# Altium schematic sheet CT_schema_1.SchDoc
size 559 x 508 mm
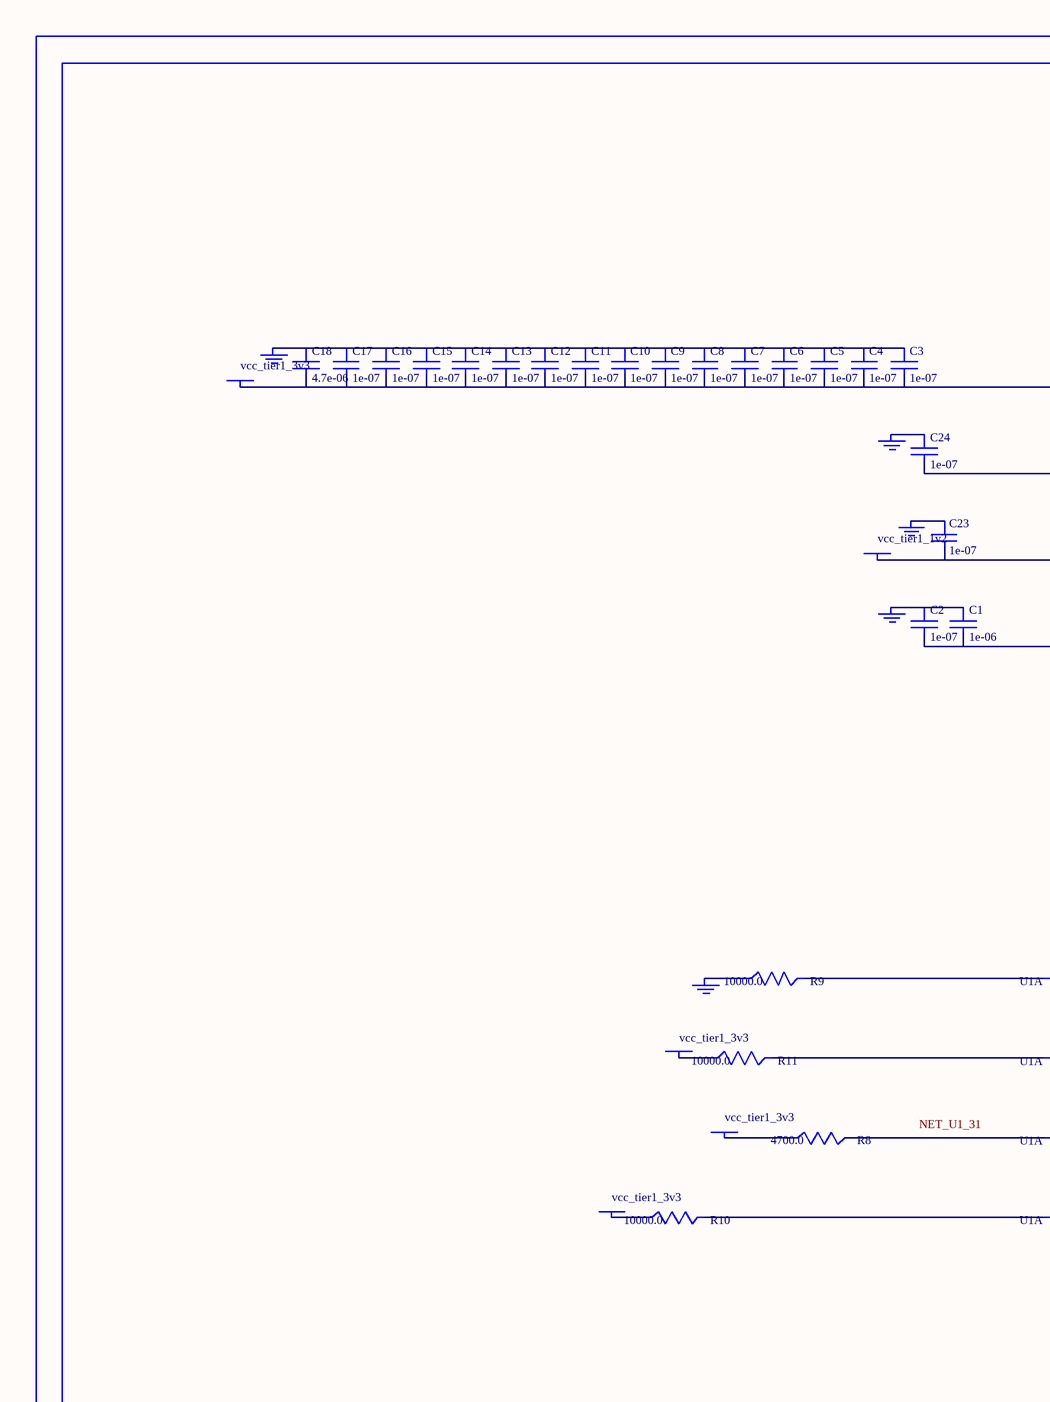
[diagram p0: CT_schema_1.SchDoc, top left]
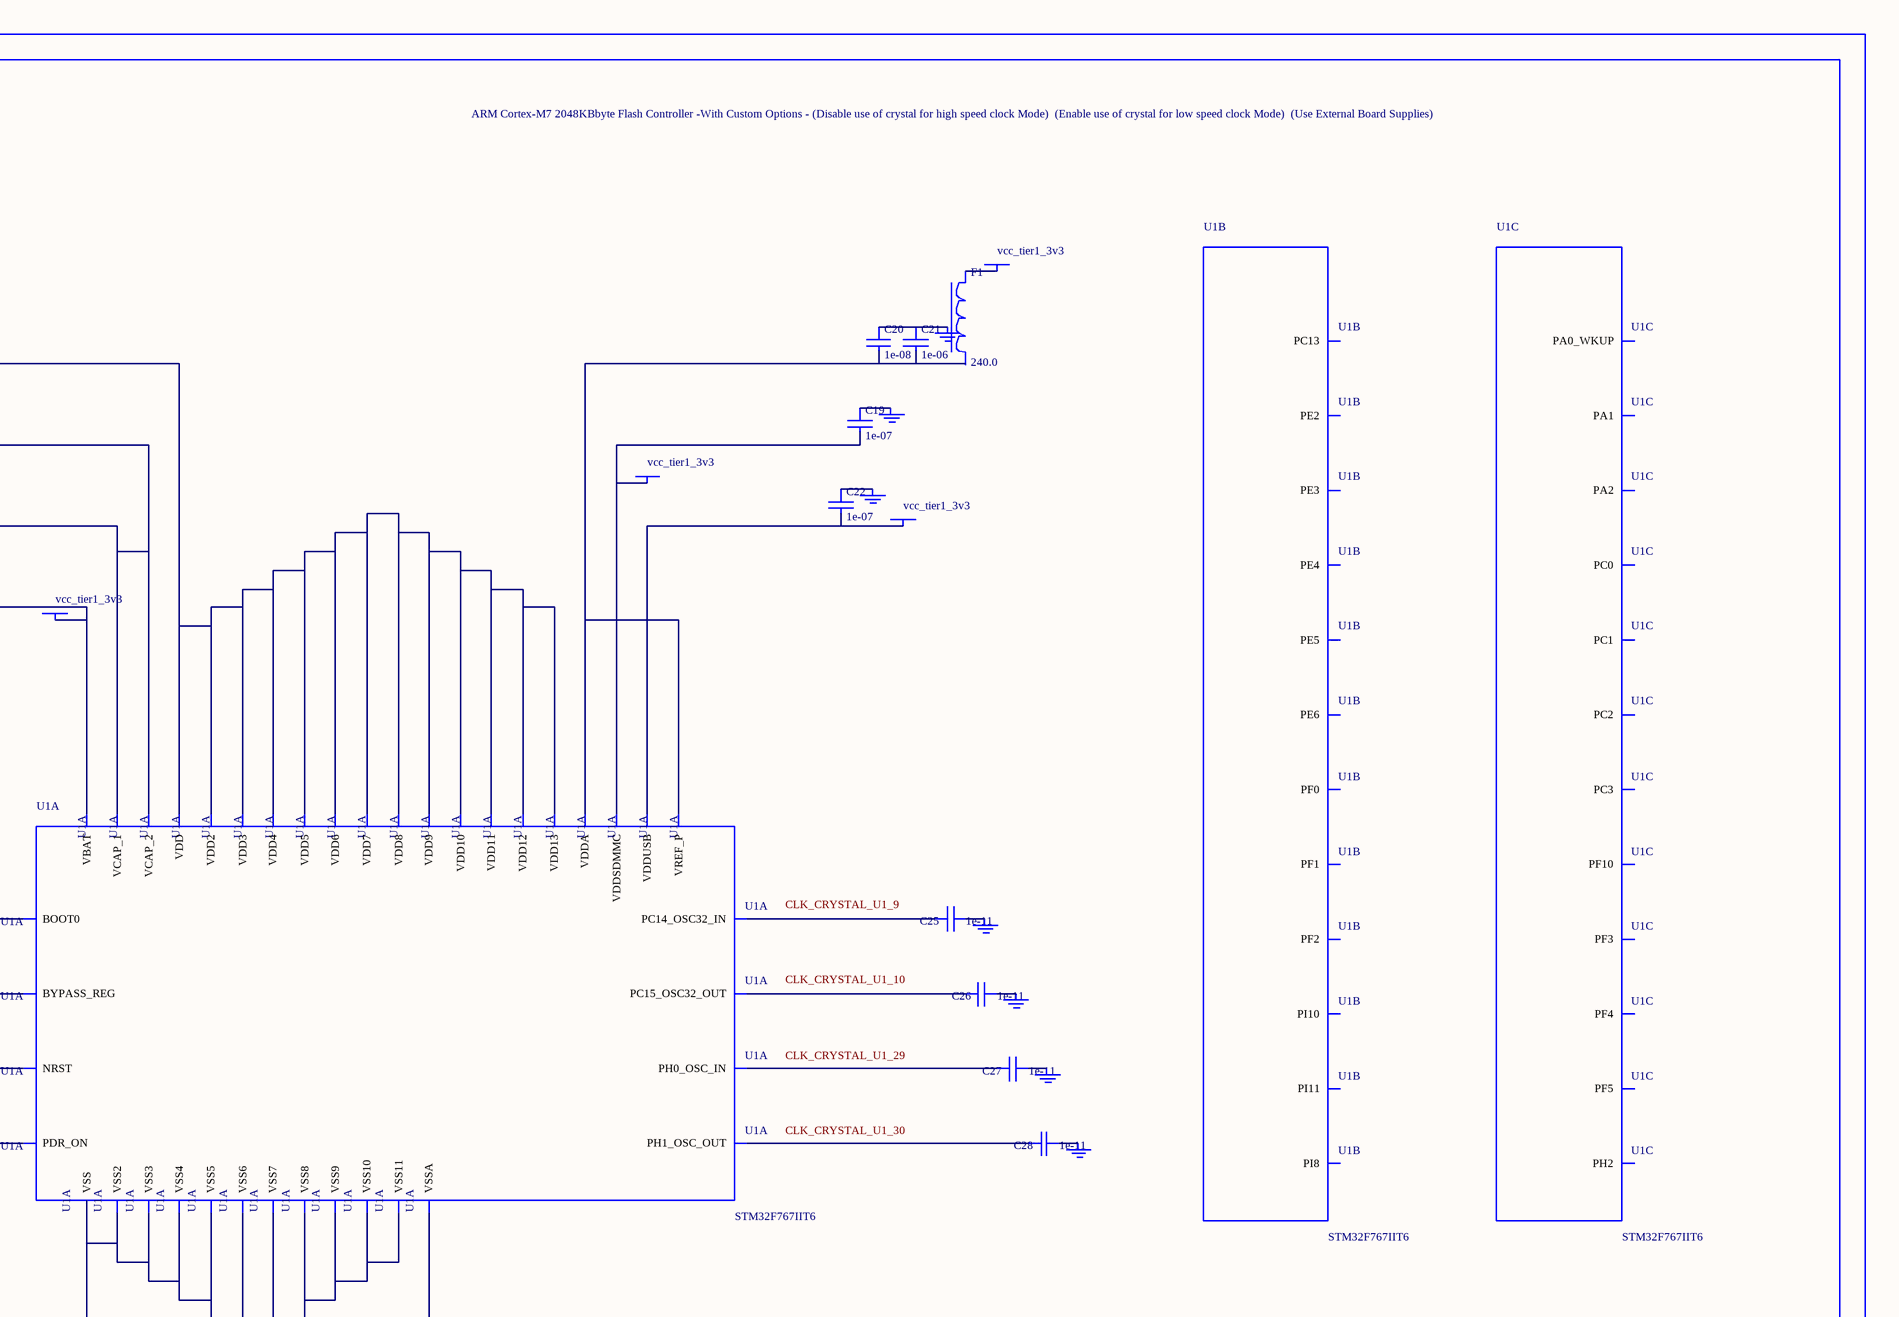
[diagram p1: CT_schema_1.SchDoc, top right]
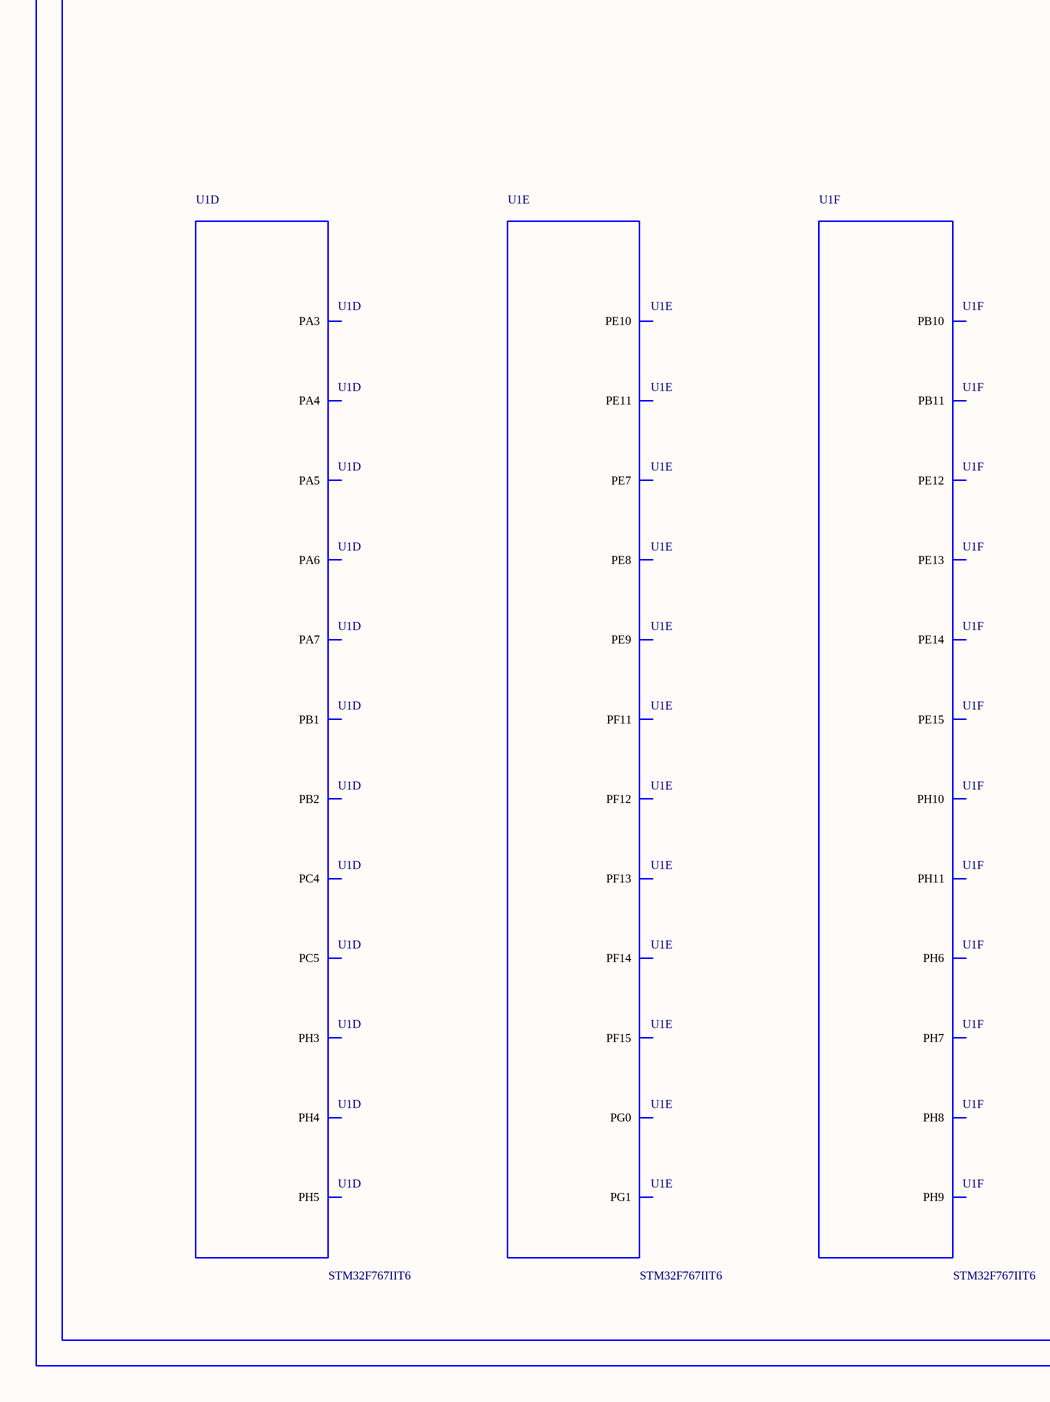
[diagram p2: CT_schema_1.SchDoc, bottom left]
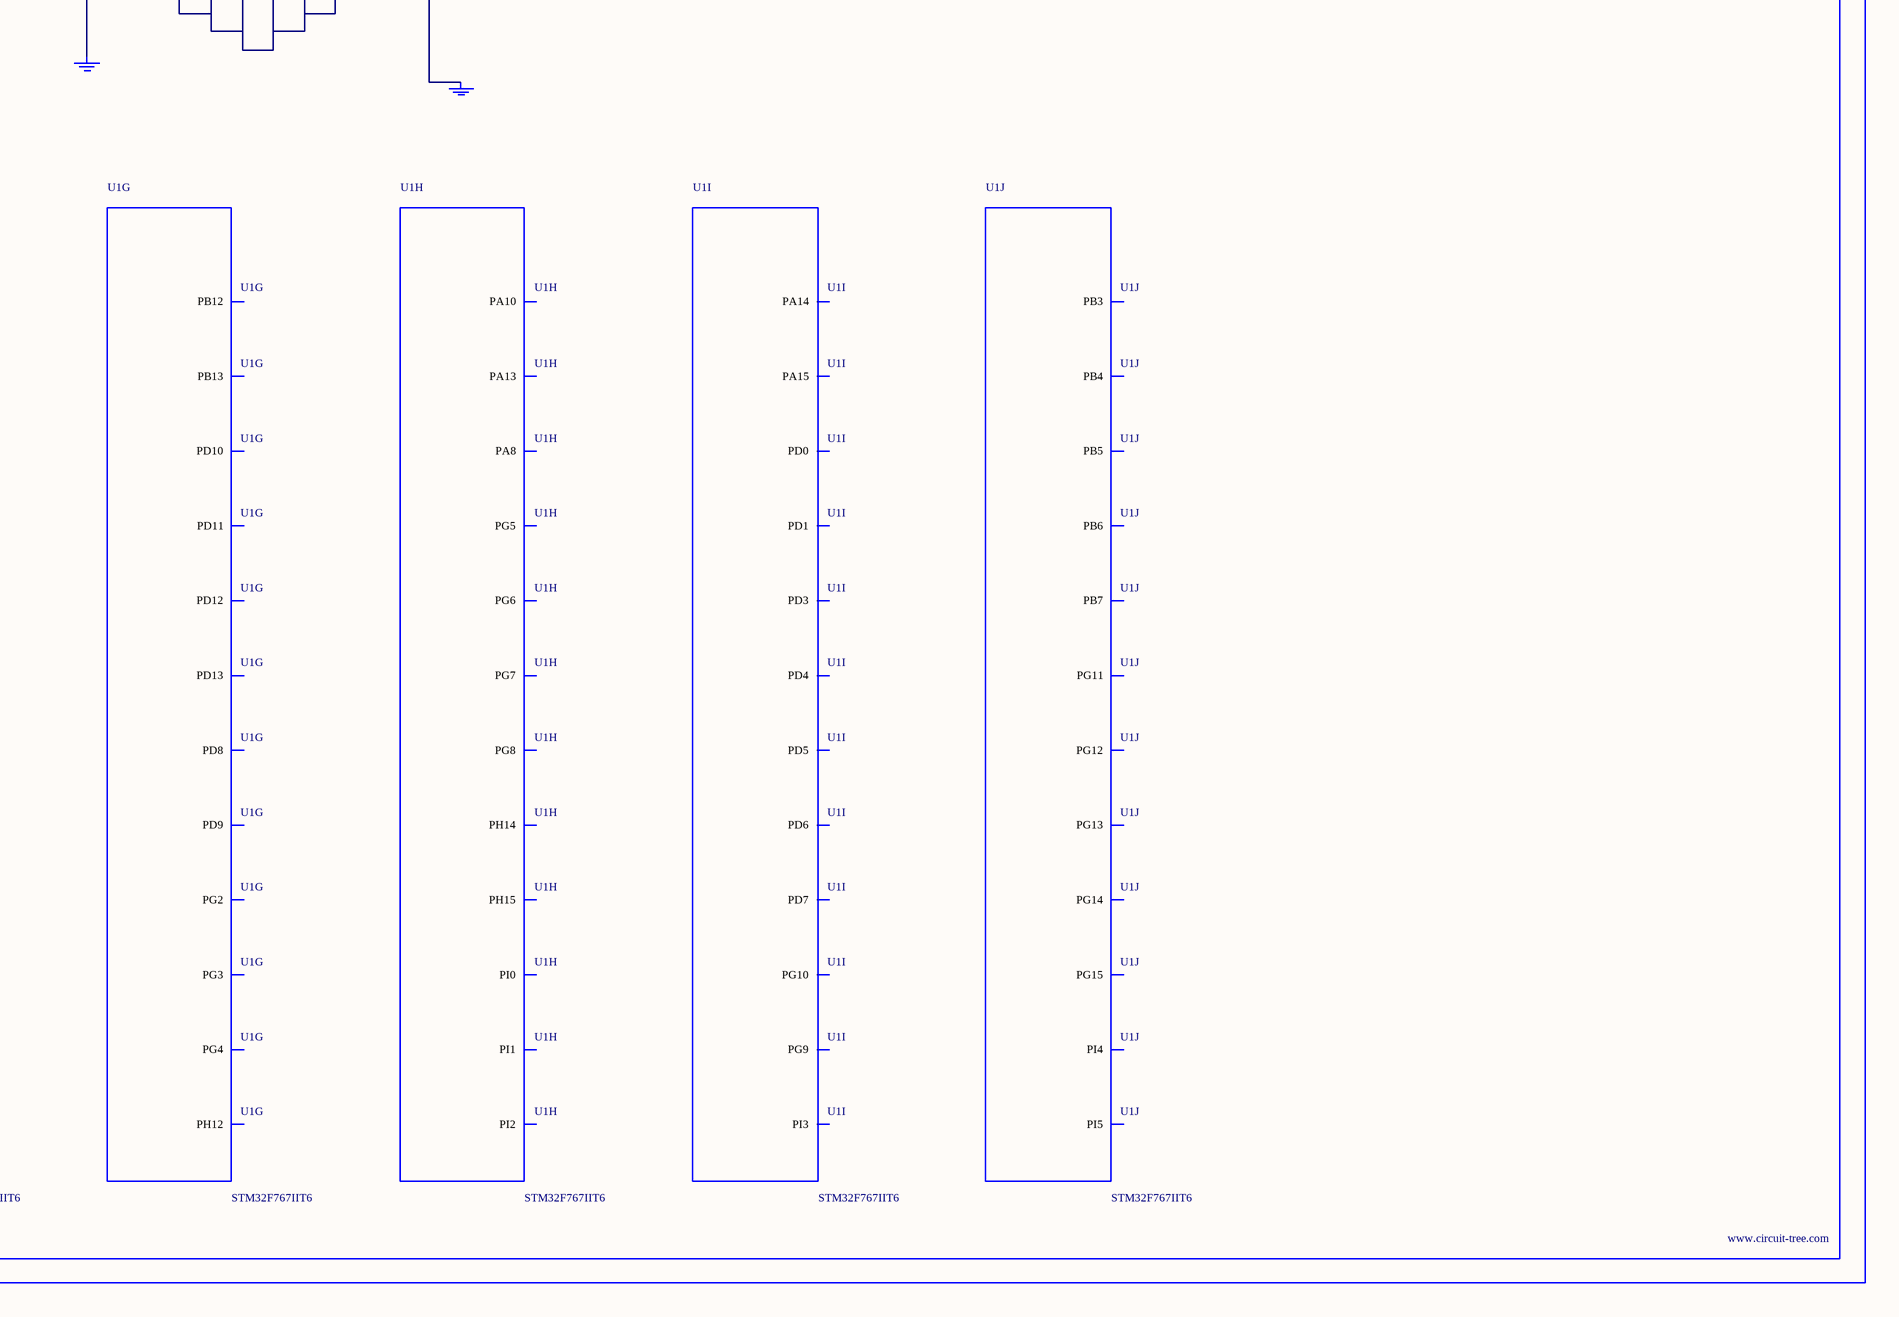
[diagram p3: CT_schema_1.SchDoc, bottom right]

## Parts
BORDER0  (no value)
C1  1e-06  [C0603]
C2  1e-07  [C0603]
C3  1e-07  [C0603]
C4  1e-07  [C0603]
C5  1e-07  [C0603]
C6  1e-07  [C0603]
C7  1e-07  [C0603]
C8  1e-07  [C0603]
C9  1e-07  [C0603]
C10  1e-07  [C0603]
C11  1e-07  [C0603]
C12  1e-07  [C0603]
C13  1e-07  [C0603]
C14  1e-07  [C0603]
C15  1e-07  [C0603]
C16  1e-07  [C0603]
C17  1e-07  [C0603]
C18  4.7e-06  [C0603]
C19  1e-07  [C0603]
C20  1e-08  [C0603]
C21  1e-06  [C0603]
C22  1e-07  [C0603]
C23  1e-07  [C0603]
C24  1e-07  [C0603]
C25  1e-11  [C0402]
C26  1e-11  [C0402]
C27  1e-11  [C0402]
C28  1e-11  [C0402]
F1  240.0  [L0603]
GND_INSTANCE_0_0  (no value)
GND_INSTANCE_0_1  (no value)
GND_INSTANCE_0_2  (no value)
GND_INSTANCE_0_3  (no value)
GND_INSTANCE_0_4  (no value)
GND_INSTANCE_0_5  (no value)
GND_INSTANCE_0_6  (no value)
GND_INSTANCE_0_7  (no value)
GND_INSTANCE_0_8  (no value)
GND_INSTANCE_0_9  (no value)
GND_INSTANCE_0_10  (no value)
GND_INSTANCE_0_11  (no value)
GND_INSTANCE_0_12  (no value)
GND_INSTANCE_0_13  (no value)
POWER_INSTANCE_0_0  vcc_tier1_3v3
POWER_INSTANCE_0_1  vcc_tier1_3v3
POWER_INSTANCE_0_2  vcc_tier1_3v3
POWER_INSTANCE_0_3  vcc_tier1_3v3
POWER_INSTANCE_0_4  vcc_tier1_1v2
POWER_INSTANCE_0_5  vcc_tier1_3v3
POWER_INSTANCE_0_6  vcc_tier1_3v3
POWER_INSTANCE_0_7  vcc_tier1_3v3
POWER_INSTANCE_0_8  vcc_tier1_3v3
R8  4700.0  [R0603]
R9  10000.0  [R0603]
R10  10000.0  [R0603]
R11  10000.0  [R0603]
U1  STM32F767IIT6  [LQFP176]  (parts A,B,C,D,E,F,G,H,I,J of 15)

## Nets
NetC1_1: C1.1 C2.1 GND_INSTANCE_0_0.0(GND)
NetC1_2: C1.2 C2.2 POWER_INSTANCE_0_0.0(PWR) U1.6(VBAT)
NetC3_1: C3.1 C4.1 C5.1 C6.1 C7.1 C8.1 C9.1 C10.1 C11.1 C12.1 C13.1 C14.1 C15.1 C16.1 C17.1 C18.1 GND_INSTANCE_0_3.0(GND)
NetC3_2: C3.2 C4.2 C5.2 C6.2 C7.2 C8.2 C9.2 C10.2 C11.2 C12.2 C13.2 C14.2 C15.2 C16.2 C17.2 C18.2 POWER_INSTANCE_0_1.0(PWR) U1.15(VDD) U1.23(VDD2) U1.36(VDD3) U1.49(VDD4) U1.62(VDD5) U1.72(VDD6) U1.82(VDD7) U1.91(VDD8) U1.103(VDD9) U1.127(VDD10) U1.136(VDD11) U1.159(VDD12) U1.172(VDD13)
NetC19_1: C19.1 GND_INSTANCE_0_11.0(GND)
NetC19_2: C19.2 POWER_INSTANCE_0_6.0(PWR) U1.149(VDDSDMMC)
NetC20_1: C20.1 C21.1 GND_INSTANCE_0_7.0(GND)
NetC20_2: C20.2 C21.2 U1.38(VREF_P) U1.39(VDDA)
NetC22_1: C22.1 GND_INSTANCE_0_9.0(GND)
NetC22_2: C22.2 POWER_INSTANCE_0_5.0(PWR) U1.114(VDDUSB)
NetC23_1: C23.1 GND_INSTANCE_0_8.0(GND)
NetC23_2: C23.2 C24.2 POWER_INSTANCE_0_4.0(PWR) U1.81(VCAP_1) U1.125(VCAP_2)
NetC24_1: C24.1 GND_INSTANCE_0_10.0(GND)
NetC25_1: C25.1 GND_INSTANCE_0_1.0(GND)
NetC25_2: C25.2 U1.9(PC14_OSC32_IN)
NetC26_1: C26.1 GND_INSTANCE_0_2.0(GND)
NetC26_2: C26.2 U1.10(PC15_OSC32_OUT)
NetC27_1: C27.1 GND_INSTANCE_0_4.0(GND)
NetC27_2: C27.2 U1.29(PH0_OSC_IN)
NetC28_1: C28.1 GND_INSTANCE_0_5.0(GND)
NetC28_2: C28.2 U1.30(PH1_OSC_OUT)
NetF1_1: F1.1 POWER_INSTANCE_0_2.0(PWR)
NetGND_INSTANCE_0_6_0: GND_INSTANCE_0_6.0(GND) U1.37(VSSA)
NetGND_INSTANCE_0_12_0: GND_INSTANCE_0_12.0(GND) R9.1
NetGND_INSTANCE_0_13_0: GND_INSTANCE_0_13.0(GND) U1.14(VSS) U1.22(VSS2) U1.61(VSS3) U1.71(VSS4) U1.90(VSS5) U1.102(VSS6) U1.113(VSS7) U1.126(VSS8) U1.135(VSS9) U1.148(VSS10) U1.158(VSS11)
NetPOWER_INSTANCE_0_3_0: POWER_INSTANCE_0_3.0(PWR) R11.1
NetPOWER_INSTANCE_0_7_0: POWER_INSTANCE_0_7.0(PWR) R10.1
NetPOWER_INSTANCE_0_8_0: POWER_INSTANCE_0_8.0(PWR) R8.1
NetR8_2: R8.2 U1.31(NRST)
NetR9_2: R9.2 U1.166(BOOT0)
NetR10_2: R10.2 U1.171(PDR_ON)
NetR11_2: R11.2 U1.48(BYPASS_REG)

Not connected (* = marked no-connect by the designer): F1 2; U1 1(PE2) 2(PE3) 3(PE4) 4(PE5) 5(PE6) 7(PI8) 8(PC13) 12(PI10) 13(PI11) 16(PF0) 17(PF1) 18(PF2) 19(PF3) 20(PF4) 21(PF5) 28(PF10) 32(PC0) 33(PC1) 34(PC2) 35(PC3) 40(PA0_WKUP) 41(PA1) 42(PA2) 43(PH2) 44(PH3) 45(PH4) 46(PH5) 47(PA3) 50(PA4) 51(PA5) 52(PA6) 53(PA7) 54(PC4) 55(PC5) 57(PB1) 58(PB2) 59(PF11) 60(PF12) 63(PF13) 64(PF14) 65(PF15) 66(PG0) 67(PG1) 68(PE7) 69(PE8) 70(PE9) 73(PE10) 74(PE11) 75(PE12) 76(PE13) 77(PE14) 78(PE15) 79(PB10) 80(PB11) 83(PH6) 84(PH7) 85(PH8) 86(PH9) 87(PH10) 88(PH11) 89(PH12) 92(PB12) 93(PB13) 96(PD8) 97(PD9) 98(PD10) 99(PD11) 100(PD12) 101(PD13) 106(PG2) 107(PG3) 108(PG4) 109(PG5) 110(PG6) 111(PG7) 112(PG8) 119(PA8) 121(PA10) 124(PA13) 129(PH14) 130(PH15) 131(PI0) 132(PI1) 133(PI2) 134(PI3) 137(PA14) 138(PA15) 142(PD0) 143(PD1) 145(PD3) 146(PD4) 147(PD5) 150(PD6) 151(PD7) 152(PG9) 153(PG10) 154(PG11) 155(PG12) 156(PG13) 157(PG14) 160(PG15) 161(PB3) 162(PB4) 163(PB5) 164(PB6) 165(PB7) 173(PI4) 174(PI5)

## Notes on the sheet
- Labels drawn without touching a wire or pin: CLK_CRYSTAL_U1_9, CLK_CRYSTAL_U1_10, CLK_CRYSTAL_U1_29, CLK_CRYSTAL_U1_30, NET_U1_31

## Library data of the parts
BORDER0 = BORDER_PAGE0
C1 C21 = C0603C105K3RACTU
C2-C17 C19 C22-C24 = 06035C104K4Z2A
C18 = GRM188R6YA475KE15D
C20 = 06035C103K4Z2A
C25-C28 = C0402C100K3GACTU
F1 = Z0603C241ASMST
GND_INSTANCE_0_0-GND_INSTANCE_0_13 = GND
POWER_INSTANCE_0_0-POWER_INSTANCE_0_8 = PWR
R8 = RC0603JR-074K7L
R9-R11 = RC0603JR-0710KL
